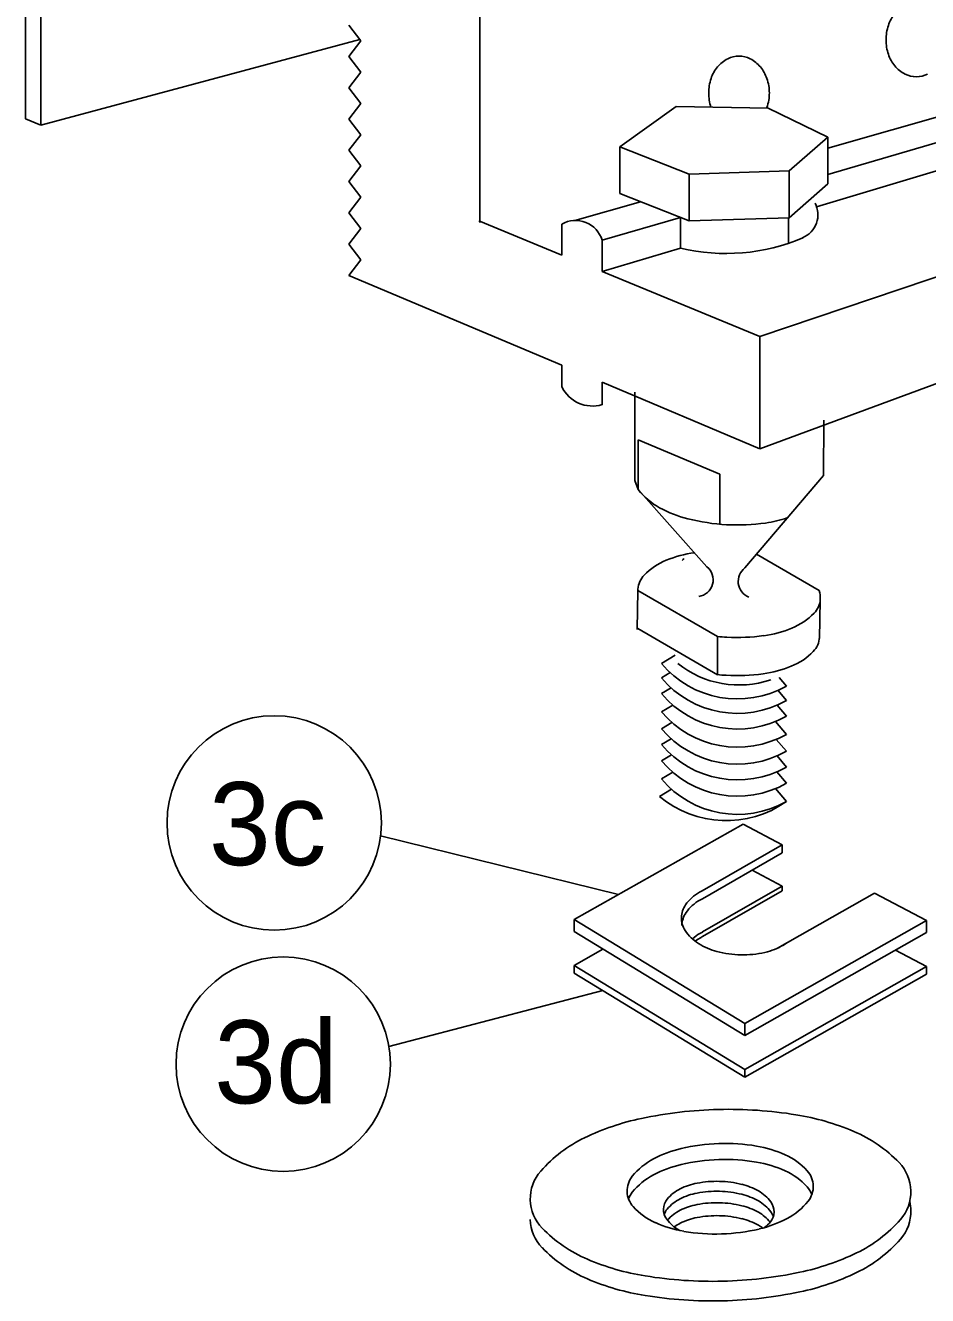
# Model space of a CAD drawing. Extents: x 12.3 to 19.6, y 5.8 to 16.1.
# Drawn here: x 13.874 to 14.807, y 7.526 to 8.839 of the extents above; entities that cross this region are included whole.
import ezdxf

# ---------------------------------------------------------------- set-up
doc = ezdxf.new("R2010")
doc.units = 0
doc.layers.add('DETL-LINE', color=7, linetype='Continuous')
doc.layers.add('DETL-NOTE', color=7, linetype='Continuous')

msp = doc.modelspace()

# ---------------------------------------------------------------- linework, layer by layer
at = {"layer": 'DETL-LINE'}
for p, q in [((13.8741, 8.7423), (13.8741, 12.9888)), ((13.8901, 8.7359), (13.8901, 12.9888)), ((14.3439, 8.6354), (14.3439, 9.0827)), ((14.221, 8.823), (14.2083, 8.8391)), ((13.8901, 8.7359), (14.2199, 8.8243)), ((14.221, 8.823), (14.2083, 8.8068)), ((14.221, 8.7906), (14.2083, 8.8068)), ((14.2083, 8.7745), (14.221, 8.7906)), ((14.221, 8.7583), (14.2083, 8.7745)), ((14.7035, 8.7119), (14.9265, 8.7755)), ((14.2083, 8.7422), (14.221, 8.7583)), ((14.7035, 8.6849), (14.9615, 8.7601)), ((14.4886, 8.7135), (14.5469, 8.7551)), ((14.5469, 8.7551), (14.6419, 8.7534)), ((14.6419, 8.7534), (14.7035, 8.7234)), ((13.8901, 8.7359), (13.8741, 8.7423)), ((14.221, 8.726), (14.2083, 8.7422)), ((14.6331, 8.5174), (15.2885, 8.7384)), ((14.692, 8.6513), (14.9615, 8.7324)), ((14.2083, 8.7099), (14.221, 8.726)), ((14.7035, 8.7234), (14.6635, 8.6885)), ((14.7035, 8.6752), (14.7035, 8.7234)), ((14.221, 8.6937), (14.2083, 8.7099)), ((14.5602, 8.6851), (14.4886, 8.7135)), ((14.4886, 8.6652), (14.4886, 8.7135)), ((14.2083, 8.6775), (14.221, 8.6937)), ((14.6635, 8.6885), (14.5602, 8.6851)), ((14.5602, 8.6368), (14.5602, 8.6851)), ((14.6635, 8.6402), (14.6635, 8.6885)), ((14.221, 8.6614), (14.2083, 8.6775)), ((14.5602, 8.6368), (14.4886, 8.6652)), ((14.7035, 8.6752), (14.6635, 8.6402)), ((14.2083, 8.6452), (14.221, 8.6614)), ((14.4422, 8.6374), (14.5099, 8.6567)), ((14.221, 8.6291), (14.2083, 8.6452)), ((14.4702, 8.6169), (14.5511, 8.6404)), ((14.5511, 8.6404), (14.5511, 8.6088)), ((14.6635, 8.6402), (14.5602, 8.6368)), ((14.6331, 8.4014), (15.2885, 8.6437)), ((14.663, 8.6139), (14.663, 8.6402)), ((14.2083, 8.6129), (14.221, 8.6291)), ((14.4286, 8.6016), (14.3429, 8.6369)), ((14.4286, 8.6335), (14.4286, 8.6016)), ((14.221, 8.5968), (14.2083, 8.6129)), ((14.4702, 8.6169), (14.4702, 8.5845)), ((14.4702, 8.5845), (14.5511, 8.6088)), ((14.2083, 8.5806), (14.221, 8.5968)), ((14.2083, 8.5806), (14.4286, 8.4877)), ((14.6331, 8.5174), (14.4702, 8.5845)), ((14.6331, 8.4014), (14.6331, 8.5174)), ((14.4286, 8.4877), (14.4286, 8.4656)), ((14.4702, 8.4701), (14.6331, 8.4014)), ((14.4702, 8.4701), (14.4702, 8.4469)), ((14.5042, 8.3686), (14.5042, 8.4597)), ((14.6995, 8.431), (14.699, 8.3739)), ((14.5075, 8.3592), (14.5075, 8.4107)), ((14.5919, 8.375), (14.5076, 8.4107)), ((14.5076, 8.3591), (14.5042, 8.3686)), ((14.5919, 8.375), (14.5919, 8.3234)), ((14.699, 8.3739), (14.6179, 8.2782)), ((14.5076, 8.3591), (14.5786, 8.2795)), ((14.6945, 8.2547), (14.6298, 8.2923)), ((14.5072, 8.255), (14.5065, 8.2144)), ((14.5894, 8.2073), (14.5072, 8.255)), ((14.6218, 8.248), (14.6218, 8.248)), ((14.6957, 8.2448), (14.6949, 8.2053)), ((14.5894, 8.1678), (14.5072, 8.2155)), ((14.5894, 8.1678), (14.5894, 8.2073)), ((14.5316, 8.1795), (14.5457, 8.1879)), ((14.5316, 8.1646), (14.5406, 8.17)), ((14.5316, 8.1483), (14.5415, 8.1543)), ((14.6533, 8.165), (14.6607, 8.1561)), ((14.6519, 8.1517), (14.6607, 8.1412)), ((14.5316, 8.1295), (14.5433, 8.1365)), ((14.6511, 8.1364), (14.6607, 8.125)), ((14.5316, 8.112), (14.5424, 8.1185)), ((14.6495, 8.1195), (14.6607, 8.1062)), ((14.5316, 8.0958), (14.5415, 8.1017)), ((14.6503, 8.101), (14.6607, 8.0887)), ((14.5316, 8.0789), (14.5419, 8.0851)), ((14.6511, 8.0839), (14.6607, 8.0724)), ((14.5316, 8.0601), (14.5433, 8.0671)), ((14.6507, 8.0675), (14.6607, 8.0556)), ((14.5296, 8.0419), (14.542, 8.0494)), ((14.6495, 8.0501), (14.6607, 8.0368)), ((14.4414, 7.9147), (14.6159, 8.0135)), ((14.6159, 8.0135), (14.6565, 7.9921)), ((14.5735, 7.9445), (14.6565, 7.9921)), ((14.574, 7.9363), (14.6565, 7.9837)), ((14.6565, 7.9921), (14.6565, 7.9837)), ((14.6252, 7.9657), (14.6565, 7.9492)), ((14.574, 7.9019), (14.6565, 7.9492)), ((14.574, 7.8971), (14.6565, 7.9445)), ((14.6565, 7.9492), (14.6565, 7.9445)), ((14.6516, 7.8852), (14.7518, 7.942)), ((14.7518, 7.942), (14.8056, 7.9137)), ((14.6178, 7.8073), (14.4414, 7.9147)), ((14.4414, 7.9147), (14.4414, 7.9023)), ((14.6178, 7.8073), (14.8056, 7.9137)), ((14.8056, 7.9137), (14.8056, 7.9013)), ((14.6178, 7.7949), (14.4414, 7.9023)), ((14.6178, 7.7949), (14.8056, 7.9013)), ((14.4414, 7.8673), (14.4709, 7.8843)), ((14.7736, 7.8831), (14.8056, 7.8663)), ((14.6178, 7.7599), (14.4414, 7.8673)), ((14.4414, 7.8673), (14.4414, 7.8594)), ((14.6178, 7.7599), (14.8056, 7.8663)), ((14.8056, 7.8663), (14.8056, 7.8584)), ((14.6178, 7.752), (14.4414, 7.8594)), ((14.6178, 7.752), (14.8056, 7.8584)), ((14.6178, 7.8073), (14.6178, 7.7949)), ((14.6178, 7.7599), (14.6178, 7.752))]:
    msp.add_line(p, q, dxfattribs=at)
for centre, radius, start, end in [((14.8027, 8.8265), 0.0386, 140.6296, 161.2281), ((14.8101, 8.824), 0.0464, 161.2281, 180), ((14.8101, 8.824), 0.0464, 180, 198.7719), ((14.6147, 8.7754), 0.0325, 116.7848, 140.6296), ((14.6117, 8.7814), 0.0259, 90, 116.7848), ((14.6117, 8.7814), 0.0259, 63.2152, 90), ((14.6087, 8.7754), 0.0325, 39.3704, 63.2152), ((14.8027, 8.8215), 0.0386, 198.7719, 219.3704), ((14.798, 8.8177), 0.0325, 219.3704, 243.2152), ((14.6268, 8.7691), 0.0464, 161.2281, 180), ((14.6194, 8.7716), 0.0386, 140.6296, 161.2281), ((14.604, 8.7716), 0.0386, 18.7719, 39.3704), ((14.5967, 8.7691), 0.0464, 360, 18.7719), ((14.795, 8.8117), 0.0259, 243.2152, 270), ((14.795, 8.8117), 0.0259, 270, 296.7848), ((14.6268, 8.7691), 0.0464, 180, 198.3711), ((14.5967, 8.7691), 0.0464, 341.2281, 360), ((14.604, 8.7666), 0.0386, 340.1243, 341.2281), ((14.6674, 8.6433), 0.0259, 292.9423, 27.5705), ((14.4429, 8.609), 0.0284, 16.0025, 120.4194), ((14.5983, 8.8047), 0.2015, 256.4552, 293.1593), ((14.4602, 8.4805), 0.035, 205.2279, 286.5944), ((14.5263, 8.3738), 0.0237, 218.0014, 218.1265), ((14.5636, 8.4031), 0.0712, 218.1265, 241.5949), ((14.5902, 8.4523), 0.1272, 241.5949, 255.8089), ((14.6103, 8.5318), 0.2092, 255.8089, 266.8798), ((14.6103, 8.5318), 0.2092, 266.8798, 277.9507), ((14.6217, 8.4506), 0.1272, 277.9507, 288.3001), ((14.5622, 8.2234), 0.0678, 112.1647, 135.6331), ((14.5823, 8.174), 0.1211, 97.9507, 112.1647), ((14.5718, 8.2714), 0.0237, 135.6331, 141.9986), ((14.5931, 8.0966), 0.1992, 97.9092, 97.9507), ((14.5675, 8.2659), 0.0175, 278.8392, 50.8345), ((14.6285, 8.2642), 0.0176, 126.9935, 247.5653), ((14.5299, 8.255), 0.0226, 135.6331, 176.8798), ((14.5299, 8.255), 0.0226, 176.8798, 179.8427), ((14.6732, 8.2472), 0.0226, 315.6331, 356.8798), ((14.6732, 8.2472), 0.0226, 356.8798, 19.4006), ((14.6408, 8.2788), 0.0678, 292.1647, 315.6331), ((14.6099, 8.4055), 0.1992, 264.0811, 266.8798), ((14.6099, 8.4055), 0.1992, 266.8798, 277.9507), ((14.6207, 8.3281), 0.1211, 277.9507, 292.1647), ((14.6724, 8.2077), 0.0226, 315.6331, 356.8798), ((14.6724, 8.2077), 0.0226, 356.8798, 3.7998), ((14.6102, 8.2457), 0.1029, 220.0991, 299.4052), ((14.6118, 8.2584), 0.1012, 231.2376, 288.847), ((14.6401, 8.2393), 0.0678, 292.1647, 315.6331), ((14.6092, 8.3661), 0.1992, 264.3037, 266.8798), ((14.6092, 8.3661), 0.1992, 266.8798, 277.9507), ((14.62, 8.2887), 0.1211, 277.9507, 292.1647), ((14.6102, 8.2308), 0.1029, 220.0991, 299.4052), ((14.6102, 8.2146), 0.1029, 220.0991, 299.4052), ((14.6102, 8.1958), 0.1029, 220.0991, 299.4052), ((14.6102, 8.1783), 0.1029, 220.0991, 299.4052), ((14.6102, 8.162), 0.1029, 220.0991, 299.4052), ((14.6102, 8.1452), 0.1029, 220.0991, 299.4052), ((14.6102, 8.1264), 0.1029, 220.0991, 299.4052), ((14.5985, 8.124), 0.1071, 229.9667, 305.5002), ((14.5938, 7.9034), 0.0458, 120.1031, 144.53), ((14.6057, 7.883), 0.0694, 117.6454, 120.1031), ((14.5756, 7.9164), 0.0234, 144.53, 178.959), ((14.5943, 7.8953), 0.0458, 120.1031, 144.53), ((14.6062, 7.8748), 0.0694, 117.6454, 120.1031), ((14.5756, 7.9164), 0.0234, 178.959, 213.3881), ((14.5761, 7.9083), 0.0234, 144.53, 178.959), ((14.5943, 7.9287), 0.0458, 213.3881, 237.815), ((14.5943, 7.8608), 0.0458, 120.1031, 132.147), ((14.5943, 7.856), 0.0458, 120.1031, 127.4654), ((14.6062, 7.8404), 0.0694, 117.6454, 120.1031), ((14.6062, 7.8356), 0.0694, 117.6454, 120.1031), ((14.6348, 7.928), 0.0458, 300.1031, 305.8377), ((14.6069, 7.9487), 0.0694, 237.815, 254.9064), ((14.6155, 7.9806), 0.1024, 254.9064, 268.959), ((14.6155, 7.9806), 0.1024, 268.959, 283.0117), ((14.6229, 7.9484), 0.0694, 283.0117, 300.1031), ((14.5648, 7.4548), 0.2601, 101.9583, 115.6669), ((14.6009, 7.2841), 0.4345, 91.3631, 101.9583), ((14.6009, 7.2841), 0.4345, 80.7679, 91.3631), ((14.6289, 7.4563), 0.2601, 67.0592, 80.7679), ((14.675, 7.5651), 0.1419, 43.8907, 67.0592), ((14.5136, 7.5613), 0.1419, 115.6669, 138.8355), ((14.597, 7.4855), 0.1979, 91.7888, 103.1512), ((14.597, 7.4855), 0.1979, 80.4264, 91.7888), ((14.6098, 7.5608), 0.1214, 65.9087, 80.4264), ((14.5554, 7.6062), 0.0691, 117.6689, 141.2983), ((14.5797, 7.5599), 0.1214, 103.1512, 117.6689), ((14.6311, 7.6086), 0.0691, 42.2793, 65.9087), ((14.4395, 7.6261), 0.0435, 138.8355, 181.3631), ((14.5797, 7.5433), 0.1214, 103.1512, 117.6689), ((14.597, 7.4689), 0.1979, 91.7888, 103.1512), ((14.597, 7.4689), 0.1979, 80.4264, 91.7888), ((14.6098, 7.5443), 0.1214, 65.9087, 80.4264), ((14.6311, 7.592), 0.0691, 42.2793, 65.9087), ((14.6643, 7.6388), 0.0242, 1.7888, 42.2793), ((14.7459, 7.6334), 0.0435, 1.3631, 43.8907), ((14.5203, 7.6343), 0.0242, 141.2983, 181.7888), ((14.5554, 7.5897), 0.0691, 117.6689, 141.2983), ((14.5814, 7.5751), 0.0685, 100.8472, 116.3613), ((14.5888, 7.5365), 0.1077, 88.4935, 100.8472), ((14.5888, 7.5365), 0.1077, 76.1398, 88.4935), ((14.5982, 7.5746), 0.0685, 60.6257, 76.1398), ((14.5203, 7.6343), 0.0242, 181.7888, 222.2793), ((14.5203, 7.6178), 0.0242, 141.2983, 160.0349), ((14.5693, 7.5995), 0.0412, 116.3613, 140.4192), ((14.5814, 7.5648), 0.0685, 100.8472, 116.3613), ((14.5888, 7.5262), 0.1077, 88.4935, 100.8472), ((14.5888, 7.5262), 0.1077, 76.1398, 88.4935), ((14.5982, 7.5643), 0.0685, 60.6257, 76.1398), ((14.6116, 7.5984), 0.0412, 36.5678, 60.6257), ((14.6643, 7.6223), 0.0242, 19.9651, 42.2793), ((14.6643, 7.6388), 0.0242, 321.2983, 1.7888), ((14.7459, 7.6334), 0.0435, 318.8355, 1.3631), ((14.4395, 7.6261), 0.0435, 181.3631, 223.8907), ((14.5535, 7.6645), 0.0691, 222.2793, 245.9087), ((14.5505, 7.6151), 0.0168, 140.4192, 178.4935), ((14.5505, 7.6151), 0.0168, 178.4935, 216.5678), ((14.5505, 7.6048), 0.0168, 140.4192, 162.1518), ((14.5693, 7.5892), 0.0412, 116.3613, 140.4192), ((14.5814, 7.5529), 0.0685, 100.8472, 116.3613), ((14.5888, 7.5144), 0.1077, 88.4935, 100.8472), ((14.5888, 7.5144), 0.1077, 76.1398, 88.4935), ((14.5982, 7.5525), 0.0685, 60.6257, 76.1398), ((14.6116, 7.5881), 0.0412, 36.5678, 60.6257), ((14.6312, 7.6129), 0.0168, 358.4935, 36.5678), ((14.6293, 7.6669), 0.0691, 297.6689, 321.2983), ((14.7459, 7.613), 0.0435, 1.3631, 13.5108), ((14.4395, 7.6057), 0.0435, 181.3631, 223.8907), ((14.5701, 7.6296), 0.0412, 216.5678, 240.6257), ((14.5693, 7.5774), 0.0412, 116.3613, 139.795), ((14.5814, 7.5395), 0.0685, 100.8472, 116.3613), ((14.5888, 7.501), 0.1077, 88.4935, 100.8472), ((14.5888, 7.501), 0.1077, 76.1398, 88.4935), ((14.5982, 7.5391), 0.0685, 60.6257, 76.1398), ((14.6116, 7.5763), 0.0412, 38.4706, 60.6257), ((14.605, 7.7132), 0.1214, 283.1512, 297.6689), ((14.6124, 7.6285), 0.0412, 308.816, 320.4192), ((14.6312, 7.6129), 0.0168, 320.4192, 358.4935), ((14.6312, 7.6026), 0.0168, 17.8482, 36.5678), ((14.6718, 7.6981), 0.1419, 295.6669, 318.8355), ((14.7459, 7.613), 0.0435, 318.8355, 1.3631), ((14.5105, 7.6943), 0.1419, 223.8907, 247.0592), ((14.5749, 7.7123), 0.1214, 245.9087, 260.4264), ((14.5693, 7.564), 0.0412, 116.3613, 126.5096), ((14.5835, 7.6534), 0.0685, 240.6257, 241.3679), ((14.5876, 7.7876), 0.1979, 260.4264, 271.7888), ((14.5876, 7.7876), 0.1979, 271.7888, 283.1512), ((14.6116, 7.5629), 0.0412, 53.2089, 60.6257), ((14.5105, 7.674), 0.1419, 223.8907, 247.0592), ((14.6718, 7.6778), 0.1419, 295.6669, 318.8355), ((14.5565, 7.8031), 0.2601, 247.0592, 260.7679), ((14.6206, 7.8046), 0.2601, 281.9583, 295.6669), ((14.5845, 7.9753), 0.4345, 271.3631, 281.9583), ((14.6206, 7.7843), 0.2601, 281.9583, 295.6669), ((14.5565, 7.7828), 0.2601, 247.0592, 260.7679), ((14.5845, 7.9753), 0.4345, 260.7679, 271.3631), ((14.5845, 7.955), 0.4345, 260.7679, 271.3631), ((14.5845, 7.955), 0.4345, 271.3631, 281.9583)]:
    msp.add_arc(centre, radius, start, end, dxfattribs=at)
at = {"layer": 'DETL-NOTE'}
for p, q in [((14.4873, 7.9407), (14.2413, 8.0013)), ((14.4709, 7.8415), (14.2499, 7.7834))]:
    msp.add_line(p, q, dxfattribs=at)
for centre in [(14.1313, 8.0146), (14.1406, 7.7653)]:
    msp.add_circle(centre, 0.1108, dxfattribs=at)

# ---------------------------------------------------------------- texts
for s, p in [('3c', (14.0639, 7.971)), ('3d', (14.0693, 7.7248))]:
    msp.add_text(s, height=0.0858, dxfattribs=at).set_placement(p)

doc.saveas('drawing.dxf')
